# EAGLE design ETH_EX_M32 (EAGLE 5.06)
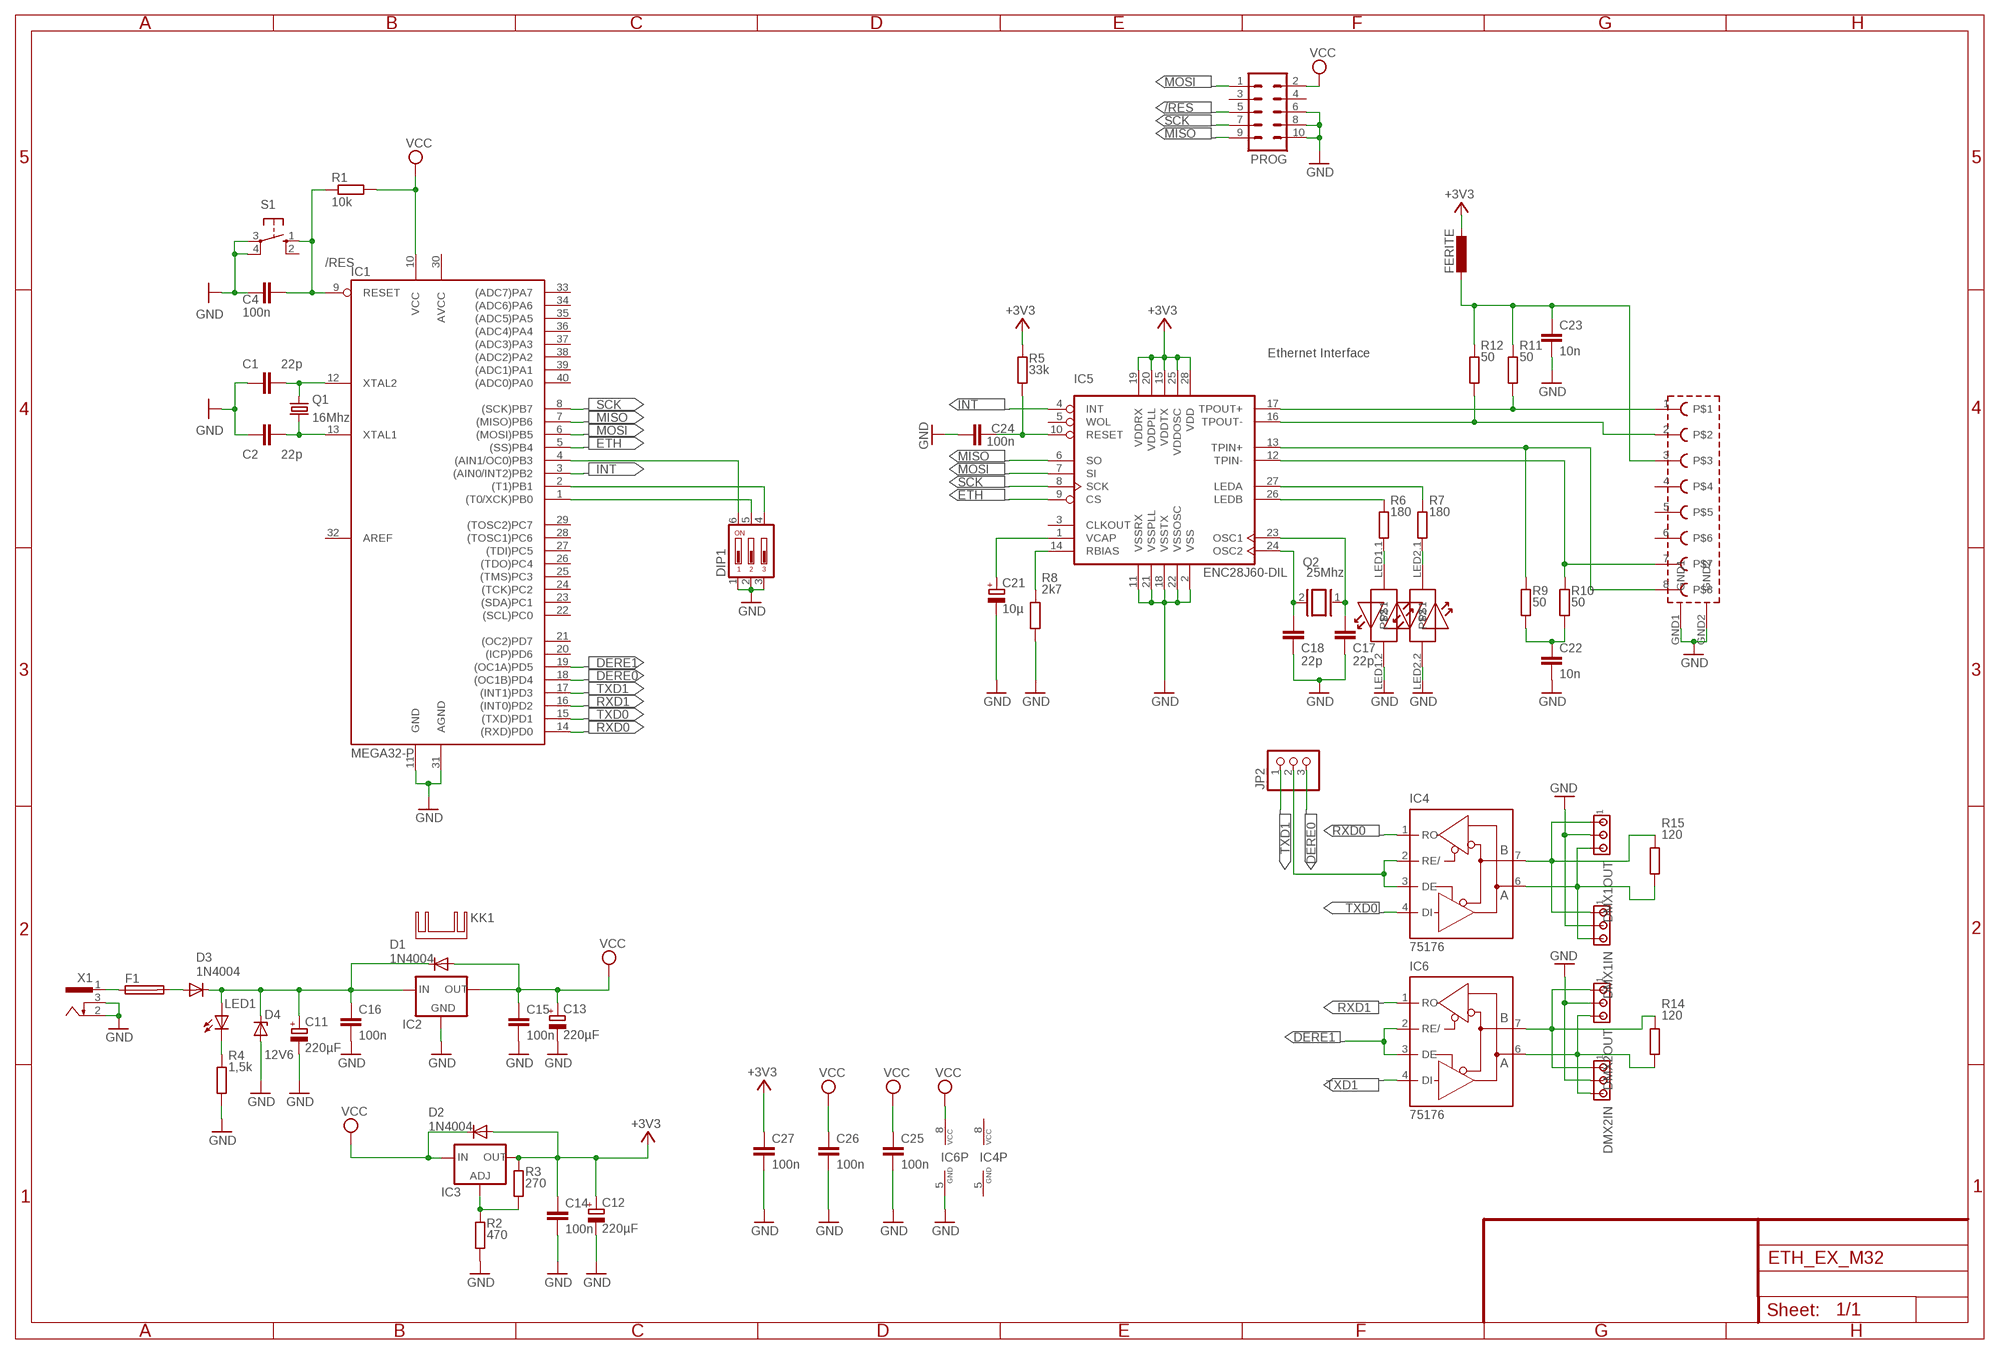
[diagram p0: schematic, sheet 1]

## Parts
C1  22p  C-EU025-024X044  [C025-024X044]
C2  22p  C-EU025-024X044  [C025-024X044]
C4  100n  C-EU025-024X044  [C025-024X044]
C11  220µF  CPOL-EUE3.5-8  [E3,5-8]
C12  220µF  CPOL-EUE3.5-8  [E3,5-8]
C13  220µF  CPOL-EUE3.5-8  [E3,5-8]
C14  100n  C-EU025-024X044  [C025-024X044]
C15  100n  C-EU050-024X044  [C050-024X044]
C16  100n  C-EU050-024X044  [C050-024X044]
C17  22p  C-EU025-024X044  [C025-024X044]
C18  22p  C-EU025-024X044  [C025-024X044]
C21  10µ  CPOL-EUE2-5  [E2-5]
C22  10n  C-EU025-025X050  [C025-025X050]
C23  10n  C-EU025-025X050  [C025-025X050]
C24  100n  C-EU025-024X044  [C025-024X044]
C25  100n  C-EU025-025X050  [C025-025X050]
C26  100n  C-EU025-025X050  [C025-025X050]
C27  100n  C-EU025-025X050  [C025-025X050]
D1  1N4004  [DO41-10]
D2  1N4004  [DO41-10]
D3  1N4004  [DO41-10]
D4  12V6  BZX90  [DO34Z7]
DIP1  DA03  [DA-03]
DMX1IN  MTA03-100  [10X03MTA]
DMX1OUT  MTA03-100  [10X03MTA]
DMX2IN  MTA03-100  [10X03MTA]
DMX2OUT  MTA03-100  [10X03MTA]
F1  PICOFUSE  [PICOFUSE]
FERITE  L-EU0204/5  [0204/5]
IC1  MEGA32-P  [DIL40]
IC2  78XXS  [78XXS]
IC3  LM317TS  [317TS]
IC4  75176  MAX481CPA  [DIL08]
IC5  ENC28J60-DIL  [DIL28-3]
IC6  75176  MAX481CPA  [DIL08]
JP2  PINHD-1X3  [1X03]
KK1  SK95-2M3  [SK95-2M3]
LED1  LED3MM  [LED3MM]
PROG  ML10  [ML10]
Q1  16Mhz  CRYTALHC49U-V  [HC49U-V]
Q2  25Mhz  XTAL/S  [QS]
R1  10k  R-EU_0207/10  [0207/10]
R2  470  R-EU_0207/10  [0207/10]
R3  270  R-EU_0207/10  [0207/10]
R4  1,5k  R-EU_0207/10  [0207/10]
R5  33k  R-EU_0207/10  [0207/10]
R6  180  R-EU_0207/10  [0207/10]
R7  180  R-EU_0207/10  [0207/10]
R8  2k7  R-EU_0207/10  [0207/10]
R9  50  R-EU_0207/10  [0207/10]
R10  50  R-EU_0207/10  [0207/10]
R11  50  R-EU_0207/10  [0207/10]
R12  50  R-EU_0207/10  [0207/10]
R14  120  R-EU_0207/10  [0207/10]
R15  120  R-EU_0207/10  [0207/10]
S1  10-XX  [B3F-10XX]
U$1  MAGJACK  [MAGJACK]
X1  SCD-014A  [SCD-014-A]

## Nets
+3V3: C12.+ C14.1 C27.1 D2.A FERITE.1 IC3.2(OUT) IC5.15(VDDTX) IC5.19(VDDRX) IC5.20(VDDPLL) IC5.25(VDDOSC) IC5.28(VDD) R3.2 R5.2
/RES: C4.2 IC1.9(RESET) PROG.5 R1.1 S1.1(S)
DERE0: IC1.18((OC1B)PD4) JP2.3
DERE1: IC1.19((OC1A)PD5) IC6.2(RE/) IC6.3(DE)
ETH: IC1.5((SS)PB4) IC5.9(CS)
GND: C1.1 C2.1 C4.1 C11.- C12.- C13.- C14.2 C15.2 C16.2 C17.1 C18.1 C21.- C22.2 C23.2 C24.1 C25.1 C26.2 C27.2 D4.A DIP1.1 DIP1.2 DIP1.3 DMX1IN.2 DMX1OUT.2 DMX2IN.2 DMX2OUT.2 IC1.11(GND) IC1.31(AGND) IC2.GND IC5.2(VSS) IC5.11(VSSRX) IC5.18(VSSTX) IC5.21(VSSPLL) IC5.22(VSSOSC) IC6.5(GND) PROG.6 PROG.8 PROG.10 R2.1 R4.1 R8.1 S1.3(P) S1.4(P1) U$1.GND1 U$1.GND2 U$1.LED1.2 U$1.LED2.2 X1.2 X1.3
INT: IC1.3((AIN0/INT2)PB2) IC5.4(INT)
MISO: IC1.7((MISO)PB6) IC5.6(SO) PROG.9
MOSI: IC1.6((MOSI)PB5) IC5.7(SI) PROG.1
N$1: C2.2 IC1.13(XTAL1) Q1.1
N$2: C1.2 IC1.12(XTAL2) Q1.2
N$3: IC4.2(RE/) IC4.3(DE) JP2.2
N$4: LED1.K(C) R4.2
N$5: DIP1.5 IC1.1((T0/XCK)PB0)
N$6: D3.A F1.2
N$8: R7.1 U$1.LED2.1
N$9: DIP1.4 IC1.2((T1)PB1)
N$10: F1.1 X1.1
N$11: IC5.27(LEDA) R7.2
N$12: IC3.1(ADJ) R2.2 R3.1
N$13: IC5.26(LEDB) R6.2
N$14: R6.1 U$1.LED1.1
N$16: DMX2IN.3 DMX2OUT.3 IC6.6(A) R14.1
N$17: DMX1IN.3 DMX1OUT.3 IC4.6(A) R15.1
N$18: DIP1.6 IC1.4((AIN1/OC0)PB3)
N$20: C18.2 IC5.24(OSC2) Q2.2
N$21: C17.2 IC5.23(OSC1) Q2.1
N$22: IC5.12(TPIN-) R10.2 U$1.7
N$23: IC5.13(TPIN+) R9.2 U$1.8
N$24: IC5.16(TPOUT-) R12.2 U$1.2
N$25: IC5.17(TPOUT+) R11.2 U$1.1
N$26: IC5.14(RBIAS) R8.2
N$27: C21.+ IC5.1(VCAP)
N$29: C22.1 R9.1 R10.1
N$30: C24.2 IC5.10(RESET) R5.1
N$31: DMX1IN.1 DMX1OUT.1 IC4.7(B) R15.2
N$32: DMX2IN.1 DMX2OUT.1 IC6.7(B) R14.2
N$248: C23.1 FERITE.2 R11.1 R12.1 U$1.3
N$250: C11.+ C16.1 D1.C D3.C D4.C IC2.IN LED1.A
RXD0: IC1.14((RXD)PD0) IC4.1(RO)
RXD1: IC1.16((INT0)PD2) IC6.1(RO)
SCK: IC1.8((SCK)PB7) IC5.8(SCK) PROG.7
TXD0: IC1.15((TXD)PD1) IC4.4(DI)
TXD1: IC1.17((INT1)PD3) IC6.4(DI) JP2.1
VCC: C13.+ C15.1 C25.2 C26.1 D1.A D2.C IC1.10(VCC) IC2.OUT IC3.3(IN) IC6.8(VCC) PROG.2 R1.2
Unconnected: IC1.20((ICP)PD6) IC1.21((OC2)PD7) IC1.22((SCL)PC0) IC1.23((SDA)PC1) IC1.24((TCK)PC2) IC1.25((TMS)PC3) IC1.26((TDO)PC4) IC1.27((TDI)PC5) IC1.28((TOSC1)PC6) IC1.29((TOSC2)PC7) IC1.33((ADC7)PA7) IC1.34((ADC6)PA6) IC1.35((ADC5)PA5) IC1.36((ADC4)PA4) IC1.37((ADC3)PA3) IC1.38((ADC2)PA2) IC1.39((ADC1)PA1) IC1.40((ADC0)PA0) IC5.3(CLKOUT) IC5.5(WOL) PROG.3 PROG.4 S1.2(S1) U$1.4 U$1.5 U$1.6

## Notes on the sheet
- Ethernet Interface

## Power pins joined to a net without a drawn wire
AREF: IC1.32(AREF)
AVCC: IC1.30(AVCC)
GND: IC4.5(GND)
VCC: IC4.8(VCC)

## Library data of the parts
C1 C2 C4 C14-C18 C22-C27 = rcl:C-EU: CAPACITOR, European symbol
C11-C13 C21 = rcl:CPOL-EU: POLARIZED CAPACITOR, European symbol
D1-D3 = diode:1N4004: DIODE
D4 = diode:BZX90: Z DIODE
DIP1 = switch-dil:DA03: DIL/CODE SWITCH
DMX1IN DMX1OUT DMX2IN DMX2OUT = con-amp:MTA03-100: AMP connector
F1 = fuse:PICOFUSE: PICOFUSE
FERITE = rcl:L-EU: INDUCTOR, European symbol
IC1 = avr-1:MEGA32-P: MICROCONTROLLER 32 Kbytes FLASH 2 Kbytes SRAM 1 Kbytes EEPROM USART 8-channel 10 bit ADC
IC2 = v-reg:78XXS: VOLTAGE REGULATOR
IC3 = v-reg:LM317TS: VOLTAGE REGULATOR
IC4 IC6 = maxim:MAX481CPA: RS485 TRANSEIVER
IC5 = enc28j60centered:ENC28J60-*: Microchip 10Mbit Ethernet controller with SPI interface Improved SOIC28 layout (pads in 0.01 raster, pin1 slightly smaller). Pin 6 (SO) changed from Out (paralleling several Outs gives an error) to OC. Author: Profi from mikrocontroller.net - forum Date: 2006.0827
JP2 = pinhead:PINHD-1X3: PIN HEADER
KK1 = heatsink:SK95-2M3: HEATSINK
LED1 = led:LED: LED
PROG = con-harting-ml:ML10: HARTING
Q1 = crystal:CRYTAL: CRYSTAL
Q2 = special:XTAL/S: CRYSTAL
R1-R12 R14 R15 = rcl:R-EU_: RESISTOR, European symbol
S1 = switch-omron:10-XX: OMRON SWITCH
U$1 = magjacksmalldrill:MAGJACK
X1 = con-shiua-chyuan:SCD-014A: Power Jack 2.5mm

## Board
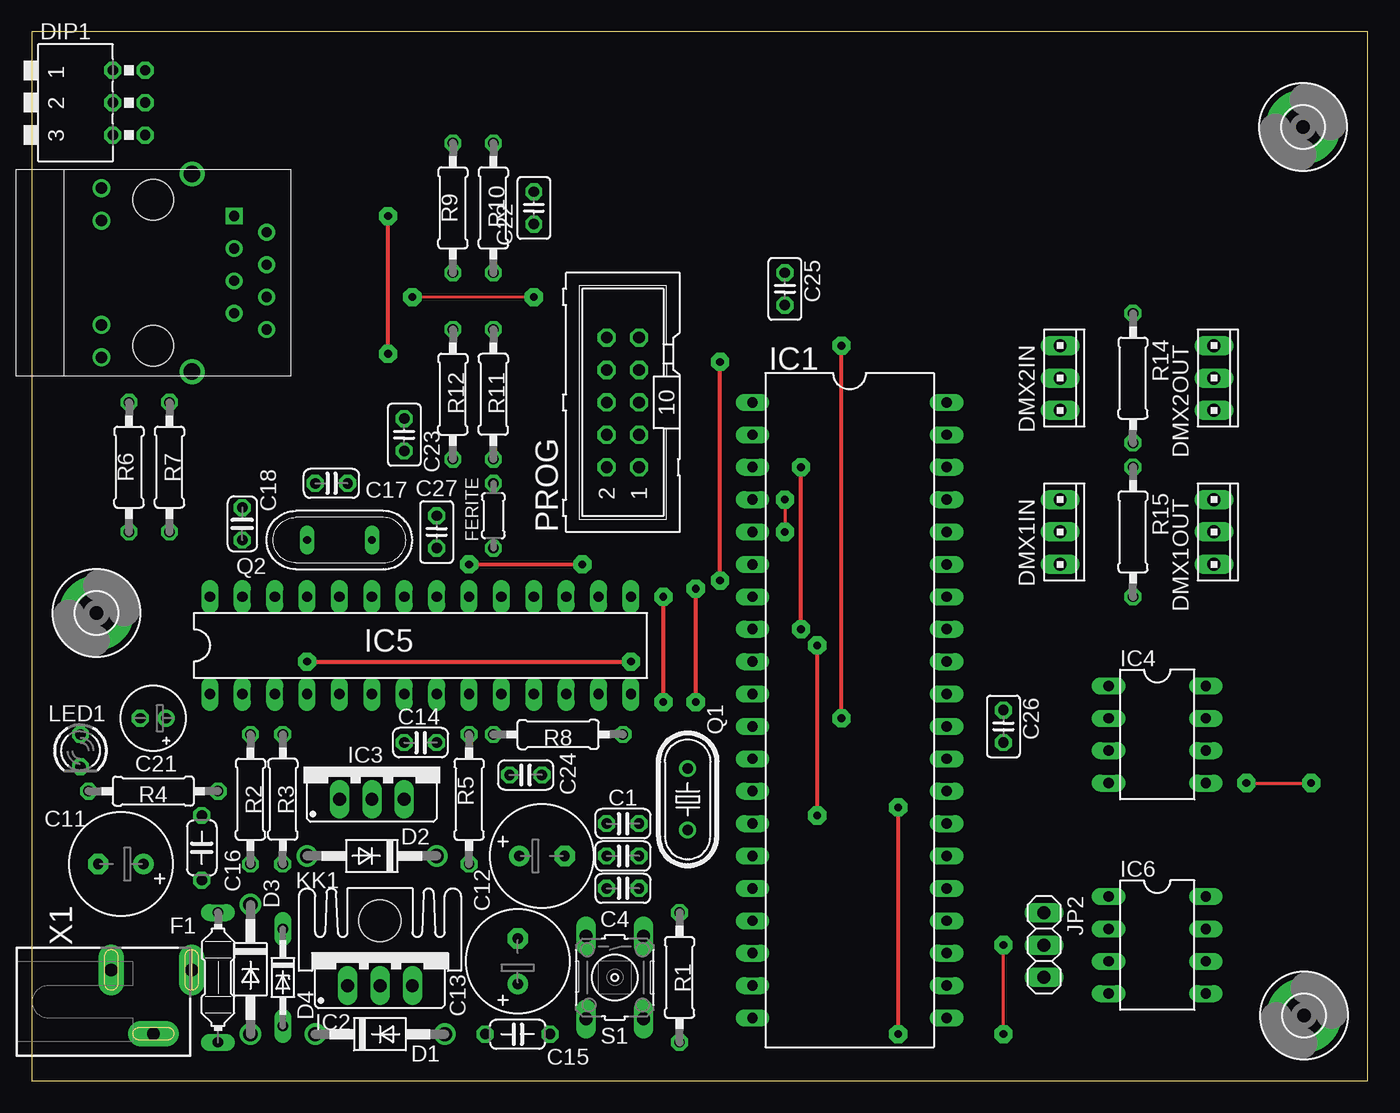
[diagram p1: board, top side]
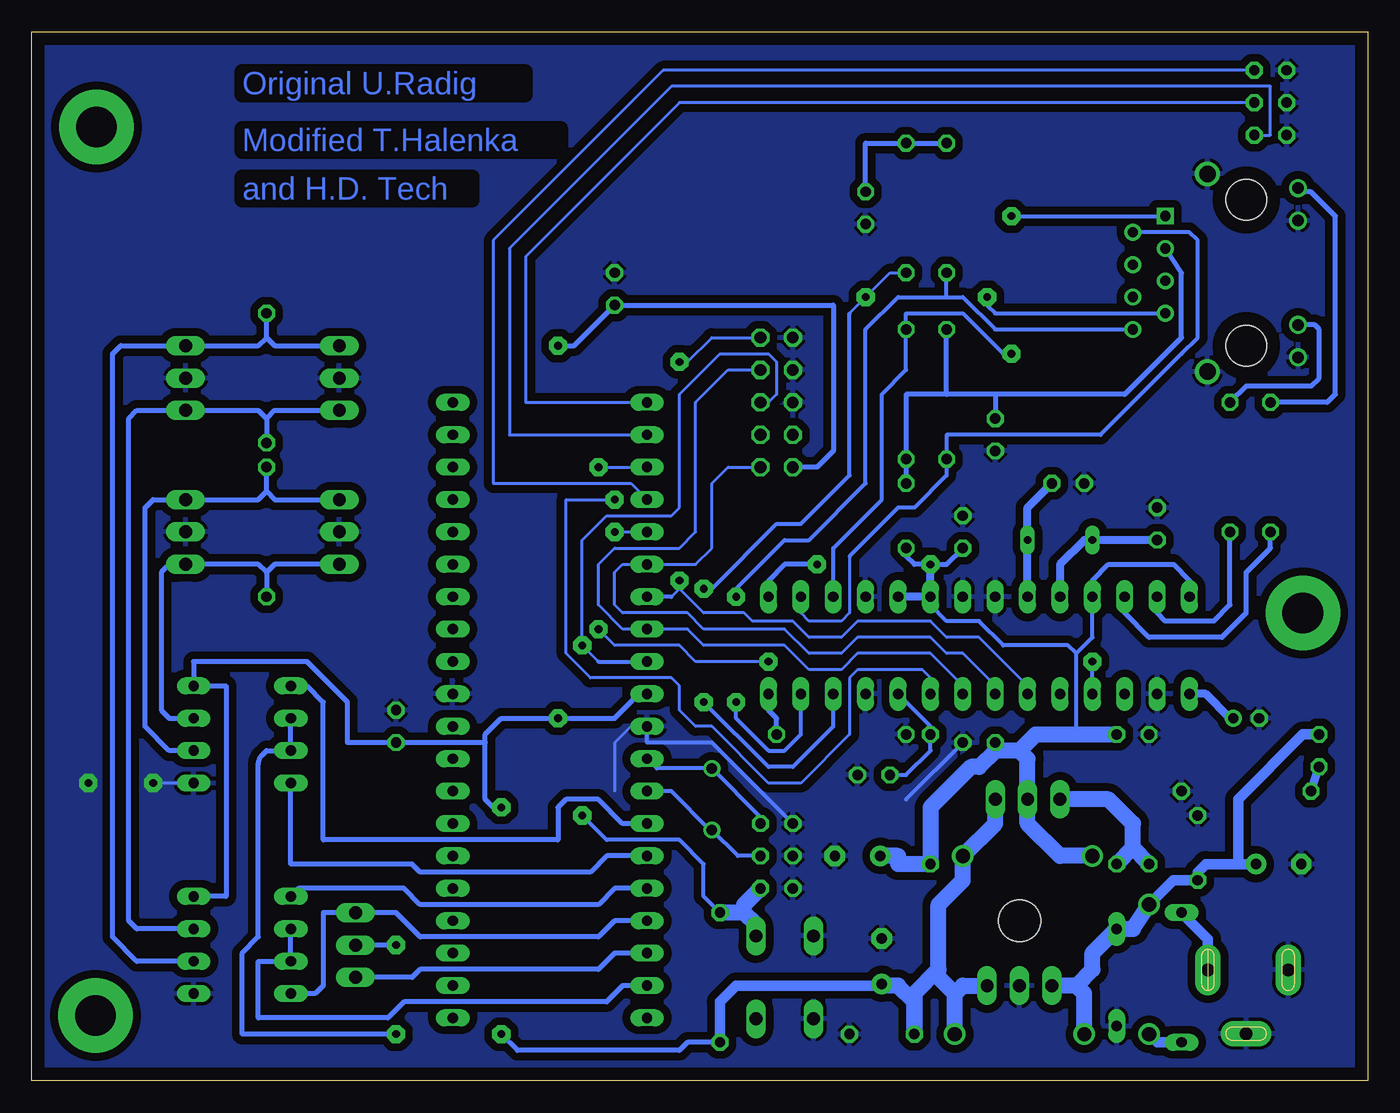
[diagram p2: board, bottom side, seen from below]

Size 104.76 x 82.22 mm. Coordinates in mm from the lower left corner, seen from the top.
Outline: 0,0 104.76,0 104.76,82.22 0,82.22 0,0
Copper layers (1*16): Top 0.035mm / dielectric 1.5mm / Bottom 0.035mm
Design rules "default": minimum track width 10mil, minimum drill 24mil, track to track 8mil, track to pad 8mil, pad to pad 8mil, via to via 8mil, smd to smd 8mil, copper to edge 40mil, drill to drill 8mil, minimum pad ring 10mil, minimum via ring 8mil, stop-mask expansion 4mil, vias tented up to drill 0mil, thermal gap 10mil

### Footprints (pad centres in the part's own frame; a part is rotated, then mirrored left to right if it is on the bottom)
C025-024X044 = drill 0.813 octagon: 1 -1.27,0; 2 1.27,0
E3,5-8 = drill 0.813 pad 1.6 round: + -1.778,0 | drill 0.813 pad 1.6 octagon: - 1.778,0
C050-024X044 = drill 0.813 octagon: 1 -2.54,0; 2 2.54,0
E2-5 = drill 0.813 pad 1.27 round: + -1.016,0 | drill 0.813 pad 1.27 octagon: - 1.016,0
C025-025X050 = drill 0.813 octagon: 1 -1.27,0; 2 1.27,0
DO41-10 = drill 1.118 round: A 5.08,0; C -5.08,0
DO34Z7 = drill 0.813 long: A 3.81,0; C -3.81,0
DA-03 = drill 0.813 octagon: 1 -2.54,-1.27; 2 0,-1.27; 3 2.54,-1.27; 4 2.54,1.27; 5 0,1.27; 6 -2.54,1.27
10X03MTA = drill 1.016 long: 1 2.54,0; 2 0,0; 3 -2.54,0
PICOFUSE = drill 0.813 long: 1 -5.08,0; 2 5.08,0
0204/5 = drill 0.813 octagon: 1 -2.54,0; 2 2.54,0
DIL40 = drill 0.813 long: 1 -24.13,-7.62; 2 -21.59,-7.62; 3 -19.05,-7.62; 4 -16.51,-7.62; 5 -13.97,-7.62; 6 -11.43,-7.62; 7 -8.89,-7.62; 8 -6.35,-7.62; 9 -3.81,-7.62; 10 -1.27,-7.62; 11 1.27,-7.62; 12 3.81,-7.62; 13 6.35,-7.62; 14 8.89,-7.62; 15 11.43,-7.62; 16 13.97,-7.62; 17 16.51,-7.62; 18 19.05,-7.62; 19 21.59,-7.62; 20 24.13,-7.62; 21 24.13,7.62; 22 21.59,7.62; 23 19.05,7.62; 24 16.51,7.62; 25 13.97,7.62; 26 11.43,7.62; 27 8.89,7.62; 28 6.35,7.62; 29 3.81,7.62; 30 1.27,7.62; 31 -1.27,7.62; 32 -3.81,7.62; 33 -6.35,7.62; 34 -8.89,7.62; 35 -11.43,7.62; 36 -13.97,7.62; 37 -16.51,7.62; 38 -19.05,7.62; 39 -21.59,7.62; 40 -24.13,7.62
78XXS = drill 1.016 long: GND 0,-2.54; IN -2.54,-2.54; OUT 2.54,-2.54
317TS = drill 1.016 long: 1 -2.54,-2.54; 2 0,-2.54; 3 2.54,-2.54
DIL08 = drill 0.813 long: 1 -3.81,-3.81; 2 -1.27,-3.81; 3 1.27,-3.81; 4 3.81,-3.81; 5 3.81,3.81; 6 1.27,3.81; 7 -1.27,3.81; 8 -3.81,3.81
DIL28-3 = drill 0.813 long: 1 -16.51,-3.81; 2 -13.97,-3.81; 3 -11.43,-3.81; 4 -8.89,-3.81; 5 -6.35,-3.81; 6 -3.81,-3.81; 7 -1.27,-3.81; 8 1.27,-3.81; 9 3.81,-3.81; 10 6.35,-3.81; 11 8.89,-3.81; 12 11.43,-3.81; 13 13.97,-3.81; 14 16.51,-3.81; 15 16.51,3.81; 16 13.97,3.81; 17 11.43,3.81; 18 8.89,3.81; 19 6.35,3.81; 20 3.81,3.81; 21 1.27,3.81; 22 -1.27,3.81; 23 -3.81,3.81; 24 -6.35,3.81; 25 -8.89,3.81; 26 -11.43,3.81; 27 -13.97,3.81; 28 -16.51,3.81
1X03 = drill 1.016 long: 1 -2.54,0; 2 0,0; 3 2.54,0
SK95-2M3 = hole 3.302: 0,2.54
LED3MM = drill 0.813 octagon: A -1.27,0; K 1.27,0
ML10 = drill 0.914 octagon: 1 -5.08,-1.27; 2 -5.08,1.27; 3 -2.54,-1.27; 4 -2.54,1.27; 5 0,-1.27; 6 0,1.27; 7 2.54,-1.27; 8 2.54,1.27; 9 5.08,-1.27; 10 5.08,1.27
HC49U-V = drill 0.813 round: 1 -2.413,0; 2 2.413,0
QS = drill 0.61 long: 1 -2.54,0; 2 2.54,0
0207/10 = drill 0.813 octagon: 1 -5.08,0; 2 5.08,0
B3F-10XX = drill 1.016 long: 1 -3.251,2.261; 2 3.251,2.261; 3 -3.251,-2.261; 4 3.251,-2.261
MAGJACK = drill 0.8 square: 1 -4.445,6.35 | drill 0.8 round: 2 -3.175,8.89; 3 -1.905,6.35; 4 -0.635,8.89; 5 0.635,6.35; 6 1.905,8.89; 7 3.175,6.35; 8 4.445,8.89 | drill 1.3 round: GND1 -7.747,3.048; GND2 7.747,3.048 | drill 0.9 round: LED1.1 -6.629,-4.064; LED1.2 -4.089,-4.064; LED2.1 4.089,-4.064; LED2.2 6.629,-4.064 | hole 3.2: -5.715,0; 5.715,0
3,2-PAD = drill 3.2 pad 5.842 round: B3,2 0,0
SCD-014-A = drill 1 pad 2 long: 1 -2.5,13.8; 2 -2.5,7.5; 3 2.5,10.8

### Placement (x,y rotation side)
C1  46.35,20.15 0 top
C2  46.35,17.61 0 top
C4  46.35,15.07 0 top
C11  6.98,16.98 180 top
C12  40,17.61 0 top
C13  38.09,9.36 90 top
C14  30.48,26.5 0 top
C15  38.09,3.65 0 top
C16  13.33,18.25 90 top
C17  23.49,46.83 0 top
C18  16.51,43.65 270 top
C21  9.52,28.41 180 top
C22  39.36,68.42 270 top
C23  29.21,50.64 270 top
C24  38.73,23.96 180 top
C25  59.05,62.07 270 top
C26  76.2,27.77 90 top
C27  31.75,43.02 90 top
D1  27.3,3.65 0 top
D2  26.67,17.61 180 top
D3  17.14,8.72 270 top
D4  19.68,8.09 270 top
DIP1  7.62,76.67 270 top
DMX1IN  80.64,43.02 270 top
DMX1OUT  92.7,43.02 270 top
DMX2IN  80.64,55.08 270 top
DMX2OUT  92.7,55.08 270 top
F1  14.6,8.09 270 top
FERITE  36.19,44.29 90 top
IC1  64.13,29.04 270 top
IC2  27.3,9.99 0 top
IC3  26.67,24.6 0 top
IC4  88.26,27.14 270 top
IC5  30.48,34.12 0 top
IC6  88.26,10.63 270 top
JP2  79.37,10.63 270 top
KK1  27.3,9.99 0 top
LED1  3.81,25.87 270 top
PROG  46.35,53.18 90 top
Q1  51.43,22.06 90 top
Q2  24.12,42.38 180 top
R1  50.79,8.09 270 top
R2  17.14,22.06 270 top
R3  19.68,22.06 90 top
R4  9.52,22.7 180 top
R5  34.28,22.06 270 top
R6  7.62,48.1 270 top
R7  10.79,48.1 270 top
R8  41.27,27.14 0 top
R9  33.02,68.42 270 top
R10  36.19,68.42 270 top
R11  36.19,53.81 90 top
R12  33.02,53.81 270 top
R14  86.36,55.08 270 top
R15  86.36,43.02 270 top
S1  45.71,8.09 270 top
U$1  9.52,63.34 270 top
U$3  [3,2-PAD]  99.69,74.77 0 top
U$4  [3,2-PAD]  99.77,5.11 0 top
U$5  [3,2-PAD]  5.08,36.67 0 top
X1  -1.27,6.19 270 top

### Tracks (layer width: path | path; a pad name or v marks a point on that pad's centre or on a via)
+3V3  (via drill 0.6 pad 1.42)
  Top 0.305: v34.28,40.48 v43.17,40.48
  Bottom 0.305: IC5.25 21.59,34.76 22.86,33.49 | IC5.20 34.28,37.3 33.02,36.03 30.48,36.03 28.57,34.12 23.49,34.12 22.86,33.49 | 22.86,27.14 22.86,33.49
  Bottom 0.406: IC5.28 13.96,39.21 15.23,40.48 20.32,40.48 21.59,39.21 IC5.25 | v43.17,40.48 45.71,40.48 46.98,39.21 IC5.15 | C27.1 33.02,40.48 v34.28,40.48 | v34.28,40.48 34.92,40.48 | v34.28,40.48 35.55,40.48 36.19,41.11 FERITE.1 | IC5.20 IC5.19 IC5.20
  Bottom 0.61: IC5.19 IC5.20 v34.28,40.48
  Bottom 1.27: C12.+ 36.82,17.61 36.82,16.98 R5.2 34.28,21.43 31.11,24.6 30.48,24.6 29.21,25.87 | D2.A 24.12,17.61 26.67,20.15 IC3.2 26.67,25.23 27.3,25.87 | 29.21,25.87 C14.1 | 27.3,25.87 29.21,25.87 | R3.2 22.86,27.14 26.03,27.14 27.3,25.87
/RES  (via drill 0.6 pad 1.42)
  Top 0.305: v61.59,20.79 v61.59,34.12
  Bottom 0.254: 60.32,32.86 v61.59,34.12 61.59,42.38 59.68,44.29 54.6,44.29 53.97,44.92 53.97,53.81 50.79,56.98 46.98,56.98 46.35,56.35 46.35,53.81 46.98,53.18 PROG.5
  Bottom 0.305: 48.89,13.8 R1.1 52.06,14.44 52.06,16.98 53.97,18.88 59.68,18.88 v61.59,20.79 | 60.32,32.86 IC1.9
  Bottom 1.27: S1.1 47.98,12.26 48.89,13.17 | 48.89,13.17 R1.1 | 48.89,13.17 48.89,13.8 C4.2
DERE0
  Bottom 0.406: IC1.18 59.05,9.99 60.32,8.72 74.29,8.72 74.93,8.09 JP2.3
DERE1
  Bottom 0.406: IC1.19 58.41,7.46 59.68,6.19 75.56,6.19 76.83,4.92 86.99,4.92 86.99,9.36 IC6.3 IC6.2
ETH  (via drill 0.6 pad 1.42)
  Top 0.254: v59.05,45.55 v59.05,43.02
  Bottom 0.254: IC5.9 34.28,31.58 34.92,32.22 40,32.22 40.63,31.58 40.63,27.14 44.45,23.33 46.98,23.33 51.43,27.77 52.7,27.77 53.97,29.04 53.97,30.95 54.6,31.58 60.95,31.58 62.86,33.49 62.86,45.55 v59.05,45.55 | v59.05,43.02 IC1.5
GND  (via drill 0.6 pad 1.42)
  Top 0.254: v95.25,23.33 v100.33,23.33
  Bottom 0.254: IC1.11 57.78,27.77 59.05,26.5 59.05,22.7 | IC4.5 v95.25,23.33 | v100.33,23.33 99.69,23.33
  Bottom 0.305: C14.2 36.19,22.06 | C1.1 51.43,26.5 56.51,26.5 IC1.11
  pour Bottom (isolate 0.61): 0.63,81.75 0.63,0.47 104.14,0.47 104.14,81.75
INT  (via drill 0.6 pad 1.42)
  Top 0.305: v21.59,32.86 v46.98,32.86 | v60.32,35.4 v60.32,48.1
  Bottom 0.254: v46.98,32.86 52.7,32.86 53.97,34.12 59.05,34.12 v60.32,35.4 | v60.32,48.1 IC1.3
  Bottom 0.305: IC5.4 v21.59,32.86
MISO  (via drill 0.6 pad 1.42)
  Top 0.305: v53.97,39.21 v53.97,56.35
  Bottom 0.254: IC5.6 26.67,30.95 30.48,34.76 33.02,34.76 34.28,36.03 40,36.03 41.27,34.76 43.81,34.76 45.08,36.03 48.25,36.03 48.89,36.67 52.06,36.67 53.97,38.57 | v53.97,56.35 53.34,56.35 51.43,58.26 PROG.9 | 53.97,38.57 v53.97,39.21 | 53.97,38.57 54.6,37.94
  Bottom 0.305: 54.6,37.94 IC1.7
MOSI
  Bottom 0.254: IC5.7 29.21,30.95 31.75,33.49 33.02,33.49 34.28,34.76 40,34.76 41.27,33.49 43.81,33.49 45.71,35.4 52.06,35.4 53.34,36.67 58.41,36.67 59.05,37.3 59.05,39.84 58.41,40.48 IC1.6 52.7,40.48 51.43,41.75 51.43,46.83 50.16,48.1 PROG.1
N$1
  Bottom 0.305: C2.2 49.4,17.61 Q1.1 51.56,19.65 54.6,22.7 IC1.13
N$2
  Bottom 0.305: C1.2 47.62,20.66 Q1.2 55.75,24.47 IC1.12
N$3  (via drill 0.6 pad 1.42)
  Top 0.254: v76.2,3.65 v76.2,10.63
  Bottom 0.406: IC4.2 IC4.3 86.36,25.87 86.7,25.53 arc-45 86.99,24.82 86.99,11.26 88.26,9.99 88.26,3.65 v76.2,3.65 | v76.2,10.63 JP2.2
N$4
  Bottom 0.61: R4.2 LED1.K
N$5
  Bottom 0.254: IC1.1 66.04,53.18 66.04,64.61 53.97,76.67 DIP1.5
N$6
  Bottom 0.813: F1.2 16.51,3.01 D3.A
N$8
  Bottom 0.406: U$1.LED2.1 4.16,59.25 3.81,58.89 3.81,55.08 4.44,54.45 9.52,54.45 R7.1
N$9
  Bottom 0.254: IC1.2 67.31,50.64 67.31,65.24 54.6,77.94 7.62,77.94 7.62,74.13 DIP1.4
N$10
  Bottom 0.813: X1.1 12.52,11.09 F1.1
N$11
  Bottom 0.406: R7.2 10.79,37.3 12.06,36.03 15.87,36.03 16.51,36.67 IC5.27
N$12
  Bottom 1.27: R2.2 18.41,18.25 | 18.41,18.25 R3.1 | 18.41,18.25 18.41,20.15 20.32,22.06 IC3.1
N$13
  Bottom 0.406: IC5.26 19.05,36.67 17.14,34.76 11.42,34.76 9.52,36.67 9.52,39.84 7.62,41.75 R6.2
N$14
  Bottom 0.406: R6.1 3.17,53.18 2.54,53.81 2.54,67.78 4.44,69.69 5.18,69.69 U$1.LED1.1
N$16
  Bottom 0.406: IC6.6 96.52,9.36 98.42,11.26 98.42,56.98 97.79,57.62 DMX2OUT.3 86.99,57.62 86.36,58.26 | 86.36,58.26 85.72,57.62 DMX2IN.3 | 86.36,58.26 R14.1
N$17
  Bottom 0.406: 86.36,46.19 86.99,45.55 DMX1OUT.3 95.25,45.55 95.88,44.92 95.88,27.77 93.98,25.87 IC4.6 | 86.36,46.19 R15.1 | 86.36,46.19 85.72,45.55 DMX1IN.3
N$18
  Bottom 0.254: DIP1.6 55.24,79.21 68.58,65.88 68.58,46.83 57.78,46.83 IC1.4
N$20
  Bottom 0.61: IC5.24 24.12,40.48 22.22,42.38 Q2.2 C18.2
N$21
  Bottom 0.61: IC5.23 Q2.1 26.67,44.92 C17.2
N$22  (via drill 0.6 pad 1.42)
  Top 0.254: v39.36,61.43 v29.84,61.43
  Top 0.305: v52.06,29.68 v52.06,38.57
  Bottom 0.254: v29.84,61.43 29.84,60.8 | 40.63,60.16 v39.36,61.43 37.46,63.34 R10.2
  Bottom 0.305: IC5.12 41.9,27.77 45.08,24.6 46.98,24.6 v52.06,29.68 | v52.06,38.57 51.43,38.57 46.35,43.65 44.45,43.65 40.63,47.46 40.63,60.16 | U$1.7 29.21,60.16 29.84,60.8
N$23  (via drill 0.6 pad 1.42)
  Top 0.305: v49.52,29.68 v49.52,37.94
  Bottom 0.305: IC5.13 44.45,27.14 45.71,25.87 46.98,25.87 49.52,28.41 v49.52,29.68 | v49.52,37.94 49.52,38.57 45.71,42.38 43.81,42.38 39.36,46.83 39.36,58.89 36.82,61.43 33.02,61.43 | 33.02,61.43 R9.2 | 33.02,61.43 31.75,61.43 29.21,58.89 U$1.8
N$24
  Bottom 0.254: IC5.16 44.45,36.67 43.81,36.03 41.27,36.03 40.63,36.67 40.63,41.11
  Bottom 0.305: 40.63,41.11 36.82,44.92 35.55,44.92 33.02,47.46 R12.2 33.02,50.64 20.95,50.64 14.6,56.98 13.33,58.26 13.33,65.88 13.96,66.51 U$1.2
N$25  (via drill 0.6 pad 1.42)
  Top 0.254: 27.94,67.14 v27.94,67.78
  Top 0.305: v27.94,56.98 27.94,67.14
  Bottom 0.305: IC5.17 41.9,41.75 38.09,45.55 38.09,53.81 36.19,55.72 R11.2 36.19,60.16 31.75,60.16 28.57,56.98 v27.94,56.98 | v27.94,67.78 U$1.1
N$26
  Bottom 0.406: IC5.14 46.98,29.04 46.35,28.41 R8.2
N$27
  Bottom 0.61: C21.+ 10.79,28.41 12.69,30.31 IC5.1
N$29
  Bottom 0.406: R9.1 R10.1 39.36,73.5 C22.1
N$30
  Bottom 0.305: IC5.10 34.28,27.77 R5.1 34.28,25.87 36.19,23.96 C24.2
N$31
  Bottom 0.406: 86.36,39.84 85.72,40.48 DMX1IN.1 | 86.36,39.84 R15.2 | 86.36,39.84 86.99,40.48 DMX1OUT.1 93.98,40.48 94.61,39.84 94.61,29.04 93.98,28.41 IC4.7
N$32
  Bottom 0.406: IC6.7 96.52,11.9 97.15,12.54 97.15,51.91 96.52,52.54 DMX2OUT.1 86.99,52.54 86.36,51.91 | 86.36,51.91 85.72,52.54 DMX2IN.1 | 86.36,51.91 R14.2
N$248
  Bottom 0.406: FERITE.2 R11.1 36.19,53.81 33.02,53.81 | 29.21,53.81 19.05,53.81 14.6,58.26 14.6,63.34 U$1.3 | 29.21,53.81 33.02,53.81 | 33.02,53.81 R12.1 | 29.21,53.81 C23.1
N$250
  Bottom 0.813: LED1.A 5.08,27.14 10.15,22.06 10.15,16.98 C11.+ 12.69,16.98 13.33,16.34 C16.1 15.23,15.71 D3.C
  Bottom 1.27: 22.86,7.46 21.59,8.72 21.59,9.99 D4.C 18.41,11.9 D3.C | 22.86,7.46 IC2.IN | D1.C 22.22,6.82 22.86,7.46
RXD0
  Bottom 0.406: IC1.14 58.41,20.15 60.32,22.06 62.86,22.06 63.49,21.43 63.49,18.88 81.91,18.88 81.91,29.68 83.18,30.95 IC4.1
RXD1
  Bottom 0.406: IC1.16 59.05,15.07 60.32,13.8 74.29,13.8 75.56,15.07 83.81,15.07 IC6.1
SCK
  Bottom 0.254: IC5.8 31.75,30.95 34.28,33.49 40,33.49 41.27,32.22 43.81,32.22 45.71,34.12 52.06,34.12 53.34,35.4 IC1.8 58.41,35.4 60.32,37.3 60.32,40.48 59.05,41.75 53.97,41.75 52.7,43.02 52.7,53.18 50.16,55.72 PROG.7
TXD0
  Bottom 0.406: IC1.15 59.68,17.61 60.95,16.34 74.29,16.34 74.93,16.98 84.45,16.98 IC4.4
TXD1
  Bottom 0.406: IC1.17 59.05,12.54 60.32,11.26 74.29,11.26 76.2,13.17 JP2.1 81.91,13.17 81.91,7.46 82.55,6.82 IC6.4
VCC  (via drill 0.6 pad 1.42)
  Top 0.305: v67.94,3.65 v67.94,21.43 | v63.49,28.41 v63.49,57.62
  Bottom 0.305: 57.14,30.31 IC1.10
  Bottom 0.406: 69.21,26.5 69.21,22.06 68.58,21.43 v67.94,21.43 | 69.21,26.5 69.21,27.14 67.94,28.41 v63.49,28.41 59.05,28.41 57.14,30.31 | v67.94,3.65 66.67,2.38 53.97,2.38 53.34,3.01 R1.2 | PROG.2 43.17,48.1 41.9,49.37 41.9,60.8 C25.2 62.22,57.62 v63.49,57.62 | 69.21,26.5 C26.1 80.01,26.5 80.01,29.68 83.18,32.86 92.07,32.86 IC4.8 89.53,30.95 89.53,14.44 IC6.8
  Bottom 0.813: 38.09,7.46 49.52,7.46 50.79,6.19 R1.2
  Bottom 1.27: IC2.OUT 31.75,7.46 32.38,6.82 | D1.A 32.38,6.82 | C13.+ 38.09,7.46 36.82,7.46 35.55,6.19 C15.1 35.55,6.82 33.65,8.72 33.65,8.09 | IC3.3 29.21,20.15 D2.C 31.75,15.71 33.65,13.8 33.65,8.09 | 32.38,6.82 33.65,8.09

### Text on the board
Bottom: Original U.Radig | Modified T.Halenka | and H.D. Tech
